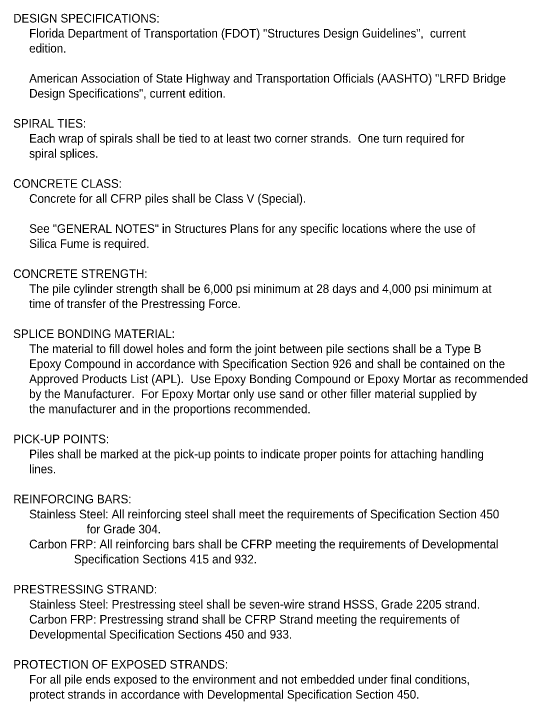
# Model space of a CAD drawing. Extents: x 120517.2 to 120592, y 120519.3 to 120603.1.
# Drawn here: x 120517.21 to 120529.25, y 120519.28 to 120535.38 of the extents above; entities that cross this region are included whole.
import ezdxf

# ---------------------------------------------------------------- set-up
doc = ezdxf.new("R2010")
doc.units = 0
doc.layers.add('PlotBorder_dp', color=7, linetype='Continuous')

msp = doc.modelspace()

# ---------------------------------------------------------------- texts
at = {"layer": 'PlotBorder_dp'}
for s, p in [('DESIGN SPECIFICATIONS:', (120517.202, 120535.176)), ('     Florida Department of Transportation (FDOT) "Structures Design Guidelines",  current', (120517.202, 120534.824)), ('     edition.', (120517.202, 120534.472)), ('     American Association of State Highway and Transportation Officials (AASHTO) "LRFD Bridge', (120517.202, 120533.768)), ('     Design Specifications", current edition.', (120517.202, 120533.416)), ('SPIRAL TIES:', (120517.202, 120532.712)), ('     Each wrap of spirals shall be tied to at least two corner strands.  One turn required for', (120517.202, 120532.36)), ('     spiral splices.', (120517.202, 120532.008)), ('CONCRETE CLASS:', (120517.202, 120531.304)), ('     Concrete for all CFRP piles shall be Class V (Special).', (120517.202, 120530.952)), ('     See "GENERAL NOTES" in Structures Plans for any specific locations where the use of ', (120517.202, 120530.248)), ('     Silica Fume is required.', (120517.202, 120529.896)), ('CONCRETE STRENGTH:', (120517.202, 120529.192)), ('     The pile cylinder strength shall be 6,000 psi minimum at 28 days and 4,000 psi minimum at', (120517.202, 120528.84)), ('     time of transfer of the Prestressing Force.', (120517.202, 120528.488)), ('SPLICE BONDING MATERIAL:', (120517.202, 120527.784)), ('     The material to fill dowel holes and form the joint between pile sections shall be a Type B', (120517.202, 120527.432)), ('     Epoxy Compound in accordance with Specification Section 926 and shall be contained on the', (120517.202, 120527.08)), ('     Approved Products List (APL).  Use Epoxy Bonding Compound or Epoxy Mortar as recommended', (120517.202, 120526.728)), ('     by the Manufacturer.  For Epoxy Mortar only use sand or other filler material supplied by', (120517.202, 120526.376)), ('     the manufacturer and in the proportions recommended. ', (120517.202, 120526.024)), ('PICK-UP POINTS:', (120517.202, 120525.32)), ('     Piles shall be marked at the pick-up points to indicate proper points for attaching handling', (120517.202, 120524.968)), ('     lines.', (120517.202, 120524.616)), ('REINFORCING BARS:', (120517.202, 120523.912)), ('     Stainless Steel: All reinforcing steel shall meet the requirements of Specification Section 450', (120517.202, 120523.56)), ('                       for Grade 304.', (120517.202, 120523.208)), ('     Carbon FRP: All reinforcing bars shall be CFRP meeting the requirements of Developmental', (120517.202, 120522.856)), ('                   Specification Sections 415 and 932.', (120517.202, 120522.504)), ('PRESTRESSING STRAND:', (120517.202, 120521.8)), ('     Stainless Steel: Prestressing steel shall be seven-wire strand HSSS, Grade 2205 strand.', (120517.202, 120521.448)), ('     Carbon FRP: Prestressing strand shall be CFRP Strand meeting the requirements of', (120517.202, 120521.096)), ('     Developmental Specification Sections 450 and 933.', (120517.202, 120520.744)), ('PROTECTION OF EXPOSED STRANDS:', (120517.202, 120520.04)), ('     For all pile ends exposed to the environment and not embedded under final conditions,', (120517.202, 120519.688)), ('     protect strands in accordance with Developmental Specification Section 450.', (120517.202, 120519.336))]:
    msp.add_text(s, height=0.2016, dxfattribs=at).set_placement(p)

doc.saveas('drawing.dxf')
